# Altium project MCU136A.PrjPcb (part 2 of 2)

## Sheet MCU136A_Connector.SchDoc
size A3; Date: Not shown in title block; ApprovedBy: Not shown in title block; CheckedBy: Not shown in title block; Author: Not shown in title block; CompanyName: Not shown in title block; Engineer: Not shown in title block; Organization: Not shown in title block; Address1: Not shown in title block; Address2: Not shown in title block; Address3: Not shown in title block; Address4: Not shown in title block; DocumentNumber: 3; Revision: Use project parameter SCH_Rev; SheetNumber: 3; SheetTotal: 5; PageSetup: Record=PageOptions¦CenterHorizontal=True¦CenterVertical=True¦PrintScale=1.00¦XCorrection=1.00¦YCorrection=1.00¦PrintKind=0¦BorderSize=5000000¦LeftOffset=0¦BottomOffset=0¦Orientation=2¦PaperLength=1000¦PaperWidth=1000¦Scale=100¦PaperSource=15¦PrintQuality=600¦MediaType=1¦DitherType=10¦PaperKind=Letter¦PrintScaleMode=1
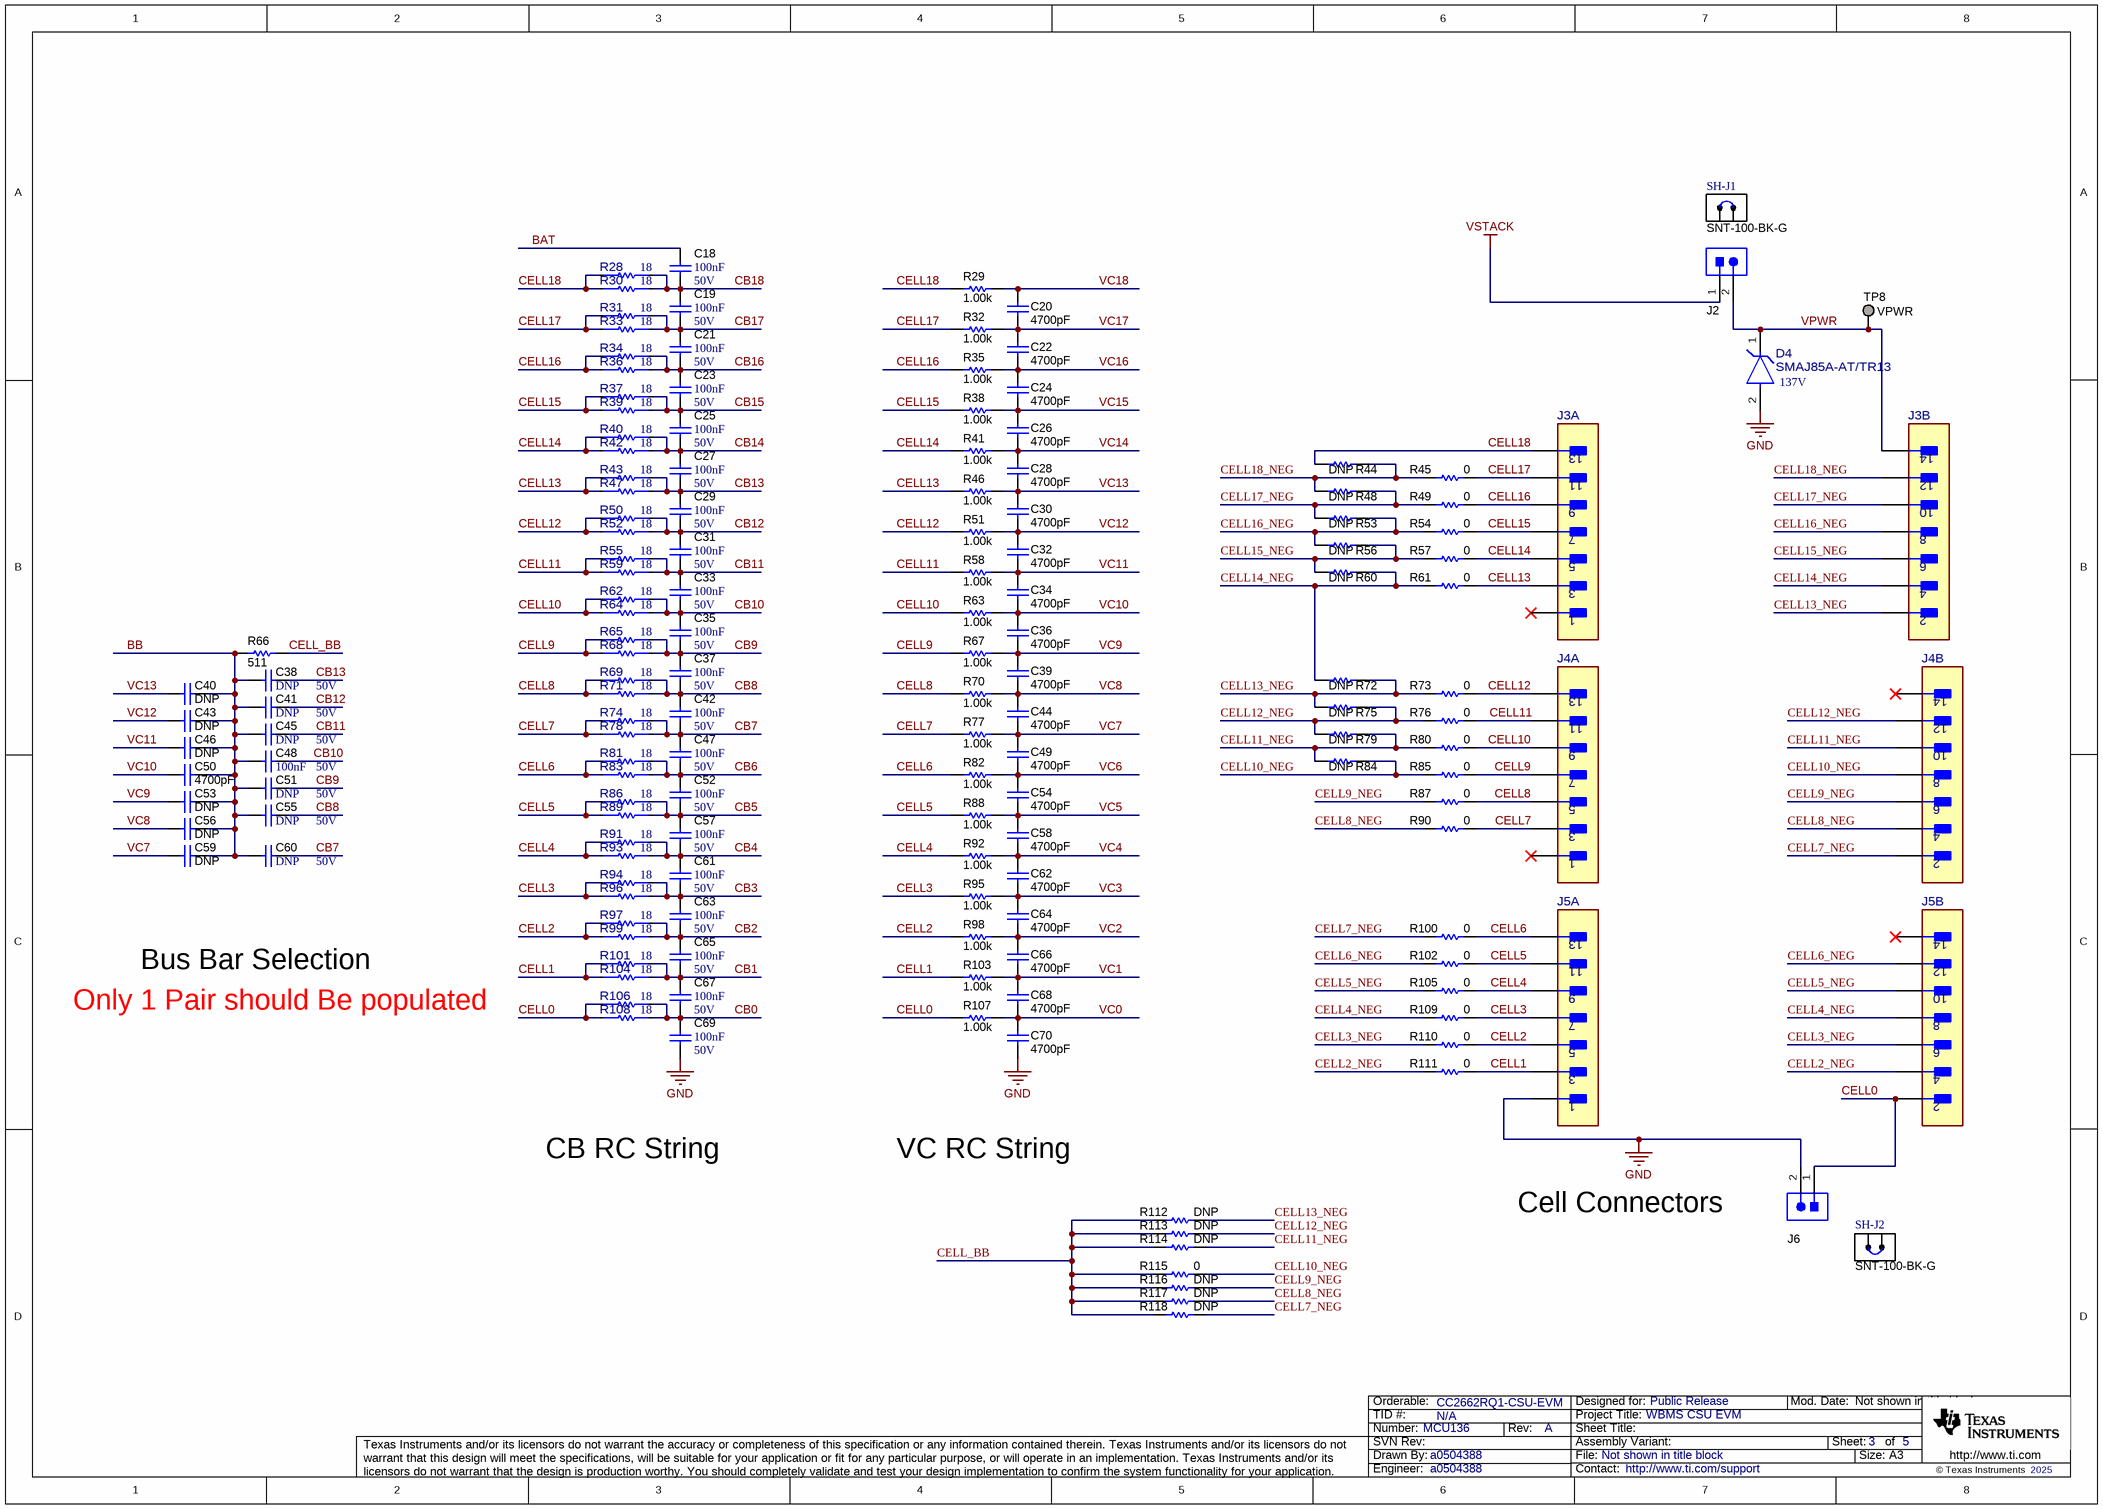
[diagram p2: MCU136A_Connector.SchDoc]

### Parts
C18  Cap_F: 100nF  VDC_V: 50V  [0603]  (hidden comment: GCM188R71H104KA57D)
C19  Cap_F: 100nF  VDC_V: 50V  [0603]  (hidden comment: GCM188R71H104KA57D)
C20  ValueDisplayed: 4700pF  [0402]  (hidden comment: GCM155R71H472KA37D)
C21  Cap_F: 100nF  VDC_V: 50V  [0603]  (hidden comment: GCM188R71H104KA57D)
C22  ValueDisplayed: 4700pF  [0402]  (hidden comment: GCM155R71H472KA37D)
C23  Cap_F: 100nF  VDC_V: 50V  [0603]  (hidden comment: GCM188R71H104KA57D)
C24  ValueDisplayed: 4700pF  [0402]  (hidden comment: GCM155R71H472KA37D)
C25  Cap_F: 100nF  VDC_V: 50V  [0603]  (hidden comment: GCM188R71H104KA57D)
C26  ValueDisplayed: 4700pF  [0402]  (hidden comment: GCM155R71H472KA37D)
C27  Cap_F: 100nF  VDC_V: 50V  [0603]  (hidden comment: GCM188R71H104KA57D)
C28  ValueDisplayed: 4700pF  [0402]  (hidden comment: GCM155R71H472KA37D)
C29  Cap_F: 100nF  VDC_V: 50V  [0603]  (hidden comment: GCM188R71H104KA57D)
C30  ValueDisplayed: 4700pF  [0402]  (hidden comment: GCM155R71H472KA37D)
C31  Cap_F: 100nF  VDC_V: 50V  [0603]  (hidden comment: GCM188R71H104KA57D)
C32  ValueDisplayed: 4700pF  [0402]  (hidden comment: GCM155R71H472KA37D)
C33  Cap_F: 100nF  VDC_V: 50V  [0603]  (hidden comment: GCM188R71H104KA57D)
C34  ValueDisplayed: 4700pF  [0402]  (hidden comment: GCM155R71H472KA37D)
C35  Cap_F: 100nF  VDC_V: 50V  [0603]  (hidden comment: GCM188R71H104KA57D)
C36  ValueDisplayed: 4700pF  [0402]  (hidden comment: GCM155R71H472KA37D)
C37  Cap_F: 100nF  VDC_V: 50V  [0603]  (hidden comment: GCM188R71H104KA57D)
C38  VDC_V: 50V  ValueDisplayed: DNP  [0603]  (hidden comment: GCM188R71H104KA57D)
C39  ValueDisplayed: 4700pF  [0402]  (hidden comment: GCM155R71H472KA37D)
C40  ValueDisplayed: DNP  [0402]  (hidden comment: GCM155R71H472KA37D)
C41  VDC_V: 50V  ValueDisplayed: DNP  [0603]  (hidden comment: GCM188R71H104KA57D)
C42  Cap_F: 100nF  VDC_V: 50V  [0603]  (hidden comment: GCM188R71H104KA57D)
C43  ValueDisplayed: DNP  [0402]  (hidden comment: GCM155R71H472KA37D)
C44  ValueDisplayed: 4700pF  [0402]  (hidden comment: GCM155R71H472KA37D)
C45  VDC_V: 50V  ValueDisplayed: DNP  [0603]  (hidden comment: GCM188R71H104KA57D)
C46  ValueDisplayed: DNP  [0402]  (hidden comment: GCM155R71H472KA37D)
C47  Cap_F: 100nF  VDC_V: 50V  [0603]  (hidden comment: GCM188R71H104KA57D)
C48  Cap_F: 100nF  VDC_V: 50V  [0603]  (hidden comment: GCM188R71H104KA57D)
C49  ValueDisplayed: 4700pF  [0402]  (hidden comment: GCM155R71H472KA37D)
C50  ValueDisplayed: 4700pF  [0402]  (hidden comment: GCM155R71H472KA37D)
C51  VDC_V: 50V  ValueDisplayed: DNP  [0603]  (hidden comment: GCM188R71H104KA57D)
C52  Cap_F: 100nF  VDC_V: 50V  [0603]  (hidden comment: GCM188R71H104KA57D)
C53  ValueDisplayed: DNP  [0402]  (hidden comment: GCM155R71H472KA37D)
C54  ValueDisplayed: 4700pF  [0402]  (hidden comment: GCM155R71H472KA37D)
C55  VDC_V: 50V  ValueDisplayed: DNP  [0603]  (hidden comment: GCM188R71H104KA57D)
C56  ValueDisplayed: DNP  [0402]  (hidden comment: GCM155R71H472KA37D)
C57  Cap_F: 100nF  VDC_V: 50V  [0603]  (hidden comment: GCM188R71H104KA57D)
C58  ValueDisplayed: 4700pF  [0402]  (hidden comment: GCM155R71H472KA37D)
C59  ValueDisplayed: DNP  [0402]  (hidden comment: GCM155R71H472KA37D)
C60  VDC_V: 50V  ValueDisplayed: DNP  [0603]  (hidden comment: GCM188R71H104KA57D)
C61  Cap_F: 100nF  VDC_V: 50V  [0603]  (hidden comment: GCM188R71H104KA57D)
C62  ValueDisplayed: 4700pF  [0402]  (hidden comment: GCM155R71H472KA37D)
C63  Cap_F: 100nF  VDC_V: 50V  [0603]  (hidden comment: GCM188R71H104KA57D)
C64  ValueDisplayed: 4700pF  [0402]  (hidden comment: GCM155R71H472KA37D)
C65  Cap_F: 100nF  VDC_V: 50V  [0603]  (hidden comment: GCM188R71H104KA57D)
C66  ValueDisplayed: 4700pF  [0402]  (hidden comment: GCM155R71H472KA37D)
C67  Cap_F: 100nF  VDC_V: 50V  [0603]  (hidden comment: GCM188R71H104KA57D)
C68  ValueDisplayed: 4700pF  [0402]  (hidden comment: GCM155R71H472KA37D)
C69  Cap_F: 100nF  VDC_V: 50V  [0603]  (hidden comment: GCM188R71H104KA57D)
C70  ValueDisplayed: 4700pF  [0402]  (hidden comment: GCM155R71H472KA37D)
D4  SMAJ85A-AT/TR13  Clamping Voltage: 137V  [FP-SMAJ85A-AT/TR13_SMA-MFG]
J2  PEC02SAAN  [CONN_PEC02SAAN]  (value not drawn)
J3  S14B-PUDSS-1(LF)(SN)  [FP-S14B-PUDSS-1(LF)(SN)_CONN_HDR14-MFG]  (value not drawn)  (parts A,B of 2)
J4  S14B-PUDSS-1(LF)(SN)  [FP-S14B-PUDSS-1(LF)(SN)_CONN_HDR14-MFG]  (value not drawn)  (parts A,B of 2)
J5  S14B-PUDSS-1(LF)(SN)  [FP-S14B-PUDSS-1(LF)(SN)_CONN_HDR14-MFG]  (value not drawn)  (parts A,B of 2)
J6  PEC02SAAN  [CONN_PEC02SAAN]  (value not drawn)
R28  value 18  [FP-CRCW120618R0FKEA_1206-MFG]  (hidden comment: CRCW120618R0FKEA)
R29  ValueDisplayed: 1.00k  [0402]  (hidden comment: CRCW04021K00FKED)
R30  value 18  [FP-CRCW120618R0FKEA_1206-MFG]  (hidden comment: CRCW120618R0FKEA)
R31  value 18  [FP-CRCW120618R0FKEA_1206-MFG]  (hidden comment: CRCW120618R0FKEA)
R32  ValueDisplayed: 1.00k  [0402]  (hidden comment: CRCW04021K00FKED)
R33  value 18  [FP-CRCW120618R0FKEA_1206-MFG]  (hidden comment: CRCW120618R0FKEA)
R34  value 18  [FP-CRCW120618R0FKEA_1206-MFG]  (hidden comment: CRCW120618R0FKEA)
R35  ValueDisplayed: 1.00k  [0402]  (hidden comment: CRCW04021K00FKED)
R36  value 18  [FP-CRCW120618R0FKEA_1206-MFG]  (hidden comment: CRCW120618R0FKEA)
R37  value 18  [FP-CRCW120618R0FKEA_1206-MFG]  (hidden comment: CRCW120618R0FKEA)
R38  ValueDisplayed: 1.00k  [0402]  (hidden comment: CRCW04021K00FKED)
R39  value 18  [FP-CRCW120618R0FKEA_1206-MFG]  (hidden comment: CRCW120618R0FKEA)
R40  value 18  [FP-CRCW120618R0FKEA_1206-MFG]  (hidden comment: CRCW120618R0FKEA)
R41  ValueDisplayed: 1.00k  [0402]  (hidden comment: CRCW04021K00FKED)
R42  value 18  [FP-CRCW120618R0FKEA_1206-MFG]  (hidden comment: CRCW120618R0FKEA)
R43  value 18  [FP-CRCW120618R0FKEA_1206-MFG]  (hidden comment: CRCW120618R0FKEA)
R44  ValueDisplayed: DNP  [0805_HV]  (hidden comment: CRCW08050000Z0EA)
R45  ValueDisplayed: 0  [0805_HV]  (hidden comment: CRCW08050000Z0EA)
R46  ValueDisplayed: 1.00k  [0402]  (hidden comment: CRCW04021K00FKED)
R47  value 18  [FP-CRCW120618R0FKEA_1206-MFG]  (hidden comment: CRCW120618R0FKEA)
R48  ValueDisplayed: DNP  [0805_HV]  (hidden comment: CRCW08050000Z0EA)
R49  ValueDisplayed: 0  [0805_HV]  (hidden comment: CRCW08050000Z0EA)
R50  value 18  [FP-CRCW120618R0FKEA_1206-MFG]  (hidden comment: CRCW120618R0FKEA)
R51  ValueDisplayed: 1.00k  [0402]  (hidden comment: CRCW04021K00FKED)
R52  value 18  [FP-CRCW120618R0FKEA_1206-MFG]  (hidden comment: CRCW120618R0FKEA)
R53  ValueDisplayed: DNP  [0805_HV]  (hidden comment: CRCW08050000Z0EA)
R54  ValueDisplayed: 0  [0805_HV]  (hidden comment: CRCW08050000Z0EA)
R55  value 18  [FP-CRCW120618R0FKEA_1206-MFG]  (hidden comment: CRCW120618R0FKEA)
R56  ValueDisplayed: DNP  [0805_HV]  (hidden comment: CRCW08050000Z0EA)
R57  ValueDisplayed: 0  [0805_HV]  (hidden comment: CRCW08050000Z0EA)
R58  ValueDisplayed: 1.00k  [0402]  (hidden comment: CRCW04021K00FKED)
R59  value 18  [FP-CRCW120618R0FKEA_1206-MFG]  (hidden comment: CRCW120618R0FKEA)
R60  ValueDisplayed: DNP  [0805_HV]  (hidden comment: CRCW08050000Z0EA)
R61  ValueDisplayed: 0  [0805_HV]  (hidden comment: CRCW08050000Z0EA)
R62  value 18  [FP-CRCW120618R0FKEA_1206-MFG]  (hidden comment: CRCW120618R0FKEA)
R63  ValueDisplayed: 1.00k  [0402]  (hidden comment: CRCW04021K00FKED)
R64  value 18  [FP-CRCW120618R0FKEA_1206-MFG]  (hidden comment: CRCW120618R0FKEA)
R65  value 18  [FP-CRCW120618R0FKEA_1206-MFG]  (hidden comment: CRCW120618R0FKEA)
R66  ValueDisplayed: 511  [0402]  (hidden comment: CRCW0402511RFKED)
R67  ValueDisplayed: 1.00k  [0402]  (hidden comment: CRCW04021K00FKED)
R68  value 18  [FP-CRCW120618R0FKEA_1206-MFG]  (hidden comment: CRCW120618R0FKEA)
R69  value 18  [FP-CRCW120618R0FKEA_1206-MFG]  (hidden comment: CRCW120618R0FKEA)
R70  ValueDisplayed: 1.00k  [0402]  (hidden comment: CRCW04021K00FKED)
R71  value 18  [FP-CRCW120618R0FKEA_1206-MFG]  (hidden comment: CRCW120618R0FKEA)
R72  ValueDisplayed: DNP  [0805_HV]  (hidden comment: CRCW08050000Z0EA)
R73  ValueDisplayed: 0  [0805_HV]  (hidden comment: CRCW08050000Z0EA)
R74  value 18  [FP-CRCW120618R0FKEA_1206-MFG]  (hidden comment: CRCW120618R0FKEA)
R75  ValueDisplayed: DNP  [0805_HV]  (hidden comment: CRCW08050000Z0EA)
R76  ValueDisplayed: 0  [0805_HV]  (hidden comment: CRCW08050000Z0EA)
R77  ValueDisplayed: 1.00k  [0402]  (hidden comment: CRCW04021K00FKED)
R78  value 18  [FP-CRCW120618R0FKEA_1206-MFG]  (hidden comment: CRCW120618R0FKEA)
R79  ValueDisplayed: DNP  [0805_HV]  (hidden comment: CRCW08050000Z0EA)
R80  ValueDisplayed: 0  [0805_HV]  (hidden comment: CRCW08050000Z0EA)
R81  value 18  [FP-CRCW120618R0FKEA_1206-MFG]  (hidden comment: CRCW120618R0FKEA)
R82  ValueDisplayed: 1.00k  [0402]  (hidden comment: CRCW04021K00FKED)
R83  value 18  [FP-CRCW120618R0FKEA_1206-MFG]  (hidden comment: CRCW120618R0FKEA)
R84  ValueDisplayed: DNP  [0805_HV]  (hidden comment: CRCW08050000Z0EA)
R85  ValueDisplayed: 0  [0805_HV]  (hidden comment: CRCW08050000Z0EA)
R86  value 18  [FP-CRCW120618R0FKEA_1206-MFG]  (hidden comment: CRCW120618R0FKEA)
R87  ValueDisplayed: 0  [0805_HV]  (hidden comment: CRCW08050000Z0EA)
R88  ValueDisplayed: 1.00k  [0402]  (hidden comment: CRCW04021K00FKED)
R89  value 18  [FP-CRCW120618R0FKEA_1206-MFG]  (hidden comment: CRCW120618R0FKEA)
R90  ValueDisplayed: 0  [0805_HV]  (hidden comment: CRCW08050000Z0EA)
R91  value 18  [FP-CRCW120618R0FKEA_1206-MFG]  (hidden comment: CRCW120618R0FKEA)
R92  ValueDisplayed: 1.00k  [0402]  (hidden comment: CRCW04021K00FKED)
R93  value 18  [FP-CRCW120618R0FKEA_1206-MFG]  (hidden comment: CRCW120618R0FKEA)
R94  value 18  [FP-CRCW120618R0FKEA_1206-MFG]  (hidden comment: CRCW120618R0FKEA)
R95  ValueDisplayed: 1.00k  [0402]  (hidden comment: CRCW04021K00FKED)
R96  value 18  [FP-CRCW120618R0FKEA_1206-MFG]  (hidden comment: CRCW120618R0FKEA)
R97  value 18  [FP-CRCW120618R0FKEA_1206-MFG]  (hidden comment: CRCW120618R0FKEA)
R98  ValueDisplayed: 1.00k  [0402]  (hidden comment: CRCW04021K00FKED)
R99  value 18  [FP-CRCW120618R0FKEA_1206-MFG]  (hidden comment: CRCW120618R0FKEA)
R100  ValueDisplayed: 0  [0805_HV]  (hidden comment: CRCW08050000Z0EA)
R101  value 18  [FP-CRCW120618R0FKEA_1206-MFG]  (hidden comment: CRCW120618R0FKEA)
R102  ValueDisplayed: 0  [0805_HV]  (hidden comment: CRCW08050000Z0EA)
R103  ValueDisplayed: 1.00k  [0402]  (hidden comment: CRCW04021K00FKED)
R104  value 18  [FP-CRCW120618R0FKEA_1206-MFG]  (hidden comment: CRCW120618R0FKEA)
R105  ValueDisplayed: 0  [0805_HV]  (hidden comment: CRCW08050000Z0EA)
R106  value 18  [FP-CRCW120618R0FKEA_1206-MFG]  (hidden comment: CRCW120618R0FKEA)
R107  ValueDisplayed: 1.00k  [0402]  (hidden comment: CRCW04021K00FKED)
R108  value 18  [FP-CRCW120618R0FKEA_1206-MFG]  (hidden comment: CRCW120618R0FKEA)
R109  ValueDisplayed: 0  [0805_HV]  (hidden comment: CRCW08050000Z0EA)
R110  ValueDisplayed: 0  [0805_HV]  (hidden comment: CRCW08050000Z0EA)
R111  ValueDisplayed: 0  [0805_HV]  (hidden comment: CRCW08050000Z0EA)
R112  ValueDisplayed: DNP  [0805_HV]  (hidden comment: CRCW08050000Z0EA)
R113  ValueDisplayed: DNP  [0805_HV]  (hidden comment: CRCW08050000Z0EA)
R114  ValueDisplayed: DNP  [0805_HV]  (hidden comment: CRCW08050000Z0EA)
R115  ValueDisplayed: 0  [0805_HV]  (hidden comment: CRCW08050000Z0EA)
R116  ValueDisplayed: DNP  [0805_HV]  (hidden comment: CRCW08050000Z0EA)
R117  ValueDisplayed: DNP  [0805_HV]  (hidden comment: CRCW08050000Z0EA)
R118  ValueDisplayed: DNP  [0805_HV]  (hidden comment: CRCW08050000Z0EA)
SH-J1  SNT-100-BK-G  [SNT-100-BK-G]
SH-J2  SNT-100-BK-G  [SNT-100-BK-G]
TP8  VPWR  [Keystone1598-2]

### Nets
GND: C69.2 C70.2 D4.2(ANODE) J5.1 J6.2
VSTACK: J2.1  [project net CELL18_Lad]
BAT: C18.1
BB: C38.1 C40.2 C41.1 C43.2 C45.1 C46.2 C48.1 C50.2 C51.1 C53.2 C55.1 C56.2 C59.2 C60.1 R66.1
CB0: C67.2 C69.1 R106.2 R108.2
CB1: C65.2 C67.1 R101.2 R104.2
CB2: C63.2 C65.1 R97.2 R99.2
CB3: C61.2 C63.1 R94.2 R96.2
CB4: C57.2 C61.1 R91.2 R93.2
CB5: C52.2 C57.1 R86.2 R89.2
CB6: C47.2 C52.1 R81.2 R83.2
CB7: C42.2 C47.1 C60.2 R74.2 R78.2
CB8: C37.2 C42.1 C55.2 R69.2 R71.2
CB9: C35.2 C37.1 C51.2 R65.2 R68.2
CB10: C33.2 C35.1 C48.2 R62.2 R64.2
CB11: C31.2 C33.1 C45.2 R55.2 R59.2
CB12: C29.2 C31.1 C41.2 R50.2 R52.2
CB13: C27.2 C29.1 C38.2 R43.2 R47.2
CB14: C25.2 C27.1 R40.2 R42.2
CB15: C23.2 C25.1 R37.2 R39.2
CB16: C21.2 C23.1 R34.2 R36.2
CB17: C19.2 C21.1 R31.2 R33.2
CB18: C18.2 C19.1 R28.2 R30.2
CELL0: J5.2 J6.1 R106.1 R107.1 R108.1
CELL1: J5.3 R101.1 R103.1 R104.1 R111.2
CELL2: J5.5 R97.1 R98.1 R99.1 R110.2
CELL2_NEG: J5.4 R111.1
CELL3: J5.7 R94.1 R95.1 R96.1 R109.2
CELL3_NEG: J5.6 R110.1
CELL4: J5.9 R91.1 R92.1 R93.1 R105.2
CELL4_NEG: J5.8 R109.1
CELL5: J5.11 R86.1 R88.1 R89.1 R102.2
CELL5_NEG: J5.10 R105.1
CELL6: J5.13 R81.1 R82.1 R83.1 R100.2
CELL6_NEG: J5.12 R102.1
CELL7: J4.3 R74.1 R77.1 R78.1 R90.2
CELL7_NEG: J4.2 R100.1 R118.2
CELL8: J4.5 R69.1 R70.1 R71.1 R87.2
CELL8_NEG: J4.4 R90.1 R117.2
CELL9: J4.7 R65.1 R67.1 R68.1 R85.2
CELL9_NEG: J4.6 R87.1 R116.2
CELL10: J4.9 R62.1 R63.1 R64.1 R80.2
CELL10_NEG: J4.8 R84.2 R85.1 R115.2
CELL11: J4.11 R55.1 R58.1 R59.1 R76.2
CELL11_NEG: J4.10 R79.2 R80.1 R84.1 R114.2
CELL12: J4.13 R50.1 R51.1 R52.1 R73.2
CELL12_NEG: J4.12 R75.2 R76.1 R79.1 R113.2
CELL13: J3.3 R43.1 R46.1 R47.1 R61.2
CELL13_NEG: J3.2 R72.2 R73.1 R75.1 R112.2
CELL14: J3.5 R40.1 R41.1 R42.1 R57.1
CELL14_NEG: J3.4 R60.2 R61.1 R72.1
CELL15: J3.7 R37.1 R38.1 R39.1 R54.1
CELL15_NEG: J3.6 R56.2 R57.2 R60.1
CELL16: J3.9 R34.1 R35.1 R36.1 R49.1
CELL16_NEG: J3.8 R53.2 R54.2 R56.1
CELL17: J3.11 R31.1 R32.1 R33.1 R45.1
CELL17_NEG: J3.10 R48.2 R49.2 R53.1
CELL18: J3.13 R28.1 R29.1 R30.1 R44.1
CELL18_NEG: J3.12 R44.2 R45.2 R48.1
CELL_BB: R66.2 R112.1 R113.1 R114.1 R115.1 R116.1 R117.1 R118.1
VC0: C68.2 C70.1 R107.2
VC1: C66.2 C68.1 R103.2
VC2: C64.2 C66.1 R98.2
VC3: C62.2 C64.1 R95.2
VC4: C58.2 C62.1 R92.2
VC5: C54.2 C58.1 R88.2
VC6: C49.2 C54.1 R82.2
VC7: C44.2 C49.1 C59.1 R77.2
VC8: C39.2 C44.1 C56.1 R70.2
VC9: C36.2 C39.1 C53.1 R67.2
VC10: C34.2 C36.1 C50.1 R63.2
VC11: C32.2 C34.1 C46.1 R58.2
VC12: C30.2 C32.1 C43.1 R51.2
VC13: C28.2 C30.1 C40.1 R46.2
VC14: C26.2 C28.1 R41.2
VC15: C24.2 C26.1 R38.2
VC16: C22.2 C24.1 R35.2
VC17: C20.2 C22.1 R32.2
VC18: C20.1 R29.2
VPWR: D4.1(CATHODE) J2.2 J3.14 TP8.1

Not connected (* = marked no-connect by the designer): J3 1*; J4 1* 14*; J5 14*

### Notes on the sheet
- Bus Bar Selection
- Only 1 Pair should Be populated
- CB RC String
- VC RC String
- Cell Connectors

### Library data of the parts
C18 C19 C21 C23 C25 C27 C29 C31 C33 C35 C37 C42 C47 C48 C52 C57 C61 C63 C65 C67 C69 = CMP-0007144-4: CAP, CERM, 0.1 uF, 50 V, +/- 10%, X7R, 0603; Manufacturer: MuRata; TaMin_C: -55°C; ESR_ohm: 0.02; Polarized: N; SizeAreaWB_mm2: 4.68; Value1: 0.02 ohm; U/M: EA; Value: 0.1uF; TaMax_C: 125°C; SizeZ_mm: 1; SizeX_mm: 1.6; SizeY_mm: 0.8; SizeArea_mm2: 1.28; IRMS_A: 1.84A; AEC Category: Q200
C20 C22 C24 C26 C28 C30 C32 C34 C36 C39 C40 C43 C44 C46 C49 C50 C53 C54 C56 C58 C59 C62 C64 C66 C68 C70 = CMP-0006361-2: CAP, CERM, 4700 pF, 50 V, +/- 10%, X7R, AEC-Q200 Grade 1, 0402; Manufacturer: MuRata; TaMin_C: -55°C; Polarized: N; SizeAreaWB_mm2: 3; Value1: Unknown; U/M: EA; Value: 4700pF; TaMax_C: 125°C; SizeZ_mm: 0.6; SizeX_mm: 1; SizeY_mm: 0.5; Value2: 50V; AEC Qualified: Y; Cap_F: 4.7nF; AEC Category: Q200
C38 C41 C45 C51 C55 C60 = CMP-0007144-4: CAP, CERM, 0.1 uF, 50 V, +/- 10%, X7R, 0603; Manufacturer: MuRata; TaMin_C: -55°C; ESR_ohm: 0.02; Polarized: N; SizeAreaWB_mm2: 4.68; Value1: 0.02 ohm; U/M: EA; Value: 0.1uF; TaMax_C: 125°C; SizeZ_mm: 1; SizeX_mm: 1.6; SizeY_mm: 0.8; SizeArea_mm2: 1.28; Cap_F: 100nF; IRMS_A: 1.84A; AEC Category: Q200
D4 = CMP-0121790-1: 137V Clamp 2.9A Ipp Tvs Diode Surface Mount DO-214AC (SMA); Manufacturer: YAGEO; AEC Qualified: Yes; SizeZ_mm: 2.5mm; VRWM: 85V; Ppk: 400W; AEC Grade: Grade 0; Breakdown Voltage: 94.4V; Direction: Unidirectional; Number Of Channels: 1; TJmax_C: +150°C
J2 J6 = CMP-0002337-1: Header, 100mil, 2x1, Tin, TH; Manufacturer: Sullins Connector Solutions; CNHeader: TRUE; Current_A: 3A; Green_Lifecycle: Not Set; Shrouded: N; Gender: Male; Green_REACh: Incomplete; Voltage_V: 1.8kV; Row_Count: 1; Pitch_mm: 2.54; CT: FALSE; Cert_UL: Y
J3-J5 = CMP-0096844-1: 14 Position Dual Row Side Entry 2 mm Through Hole Shrouded Header; Manufacturer: JST; DUT-Pitch_mm: 2mm; SizeZ_mm: 8.5mm; Row_Count: 2; ContactFinish: Tin,Copper; Current_A: 3A; Voltage_V: 250V; AEC Qualified: No; Conn Orientation: Horizontal; Conn Gender: Male
R28 R30 R31 R33 R34 R36 R37 R39 R40 R42 R43 R47 R50 R52 R55 R59 R62 R64 R65 R68 R69 R71 R74 R78 R81 R83 R86 R89 R91 R93 R94 R96 R97 R99 R101 R104 R106 R108 = CMP-0121789-1: RES Thick Film, 18Ω, 1%, 0.25W, 100ppm/°C, 1206; Manufacturer: Vishay; AEC Grade: Grade 0; AEC Qualified: Yes; Power_W: 250mW; SizeZ_mm: 0.6mm; VDC_V: 200V
R29 R32 R35 R38 R41 R46 R51 R58 R63 R67 R70 R77 R82 R88 R92 R95 R98 R103 R107 = CMP-0026071-3: RES, 1.00 k, 1%, 0.063 W, AEC-Q200 Grade 0, 0402; Manufacturer: Vishay-Dale; Power_W: 63mW; TempCo: 100 ppm/C; Value_Code: 1k00; Value: 1.00k; EIA_Code: E96; Res_ohm: 1k; SizeX_mm: 1; SizeY_mm: 0.5; SizeZ_mm: 0.6; Value2: 0.063W; AEC Qualified: Y; VDC_V: 50V; AEC Category: Q200; AEC Grade: 0
R44 R45 R48 R49 R53 R54 R56 R57 R60 R61 R72 R73 R75 R76 R79 R80 R84 R85 R87 R90 R100 R102 R105 R109-R118 = CMP-0020442-3: RES, 0, 5%, 0.125 W, AEC-Q200 Grade 0, 0805; Manufacturer: Vishay-Dale; Power_W: 125mW; TempCo: 200 ppm/C; Value_Code: 0000; Value: 0; EIA_Code: E24; SizeX_mm: 2; SizeY_mm: 1.25; SizeZ_mm: 1.45; Value2: 0.125W; SizeArea_mm2: 2.5; AEC Qualified: Y; VDC_V: 150V; AEC Category: Q200
R66 = CMP-0026436-2: RES, 511, 1%, 0.063 W, AEC-Q200 Grade 0, 0402; Manufacturer: Vishay-Dale; Power_W: 63mW; TempCo: 100 ppm/C; Value_Code: 511R; Value: 511; EIA_Code: E96; SizeX_mm: 1; SizeY_mm: 0.5; SizeZ_mm: 0.6; Value2: 0.063W; AEC Qualified: Y; VDC_V: 50V; AEC Category: Q200; AEC Grade: 0
SH-J1 SH-J2 = CMP-0003623-3: Shunt, 100mil, Gold plated, Black; Alternate PartNumber: 969102-0000-DA; Manufacturer: Samtec; Alternate Manufacturer: 3M; Value: 1x2; Note: You can "mate" this to a header by matching the designator.  i.e. use SH-J3 for header J3
TP8 = CMP-0055121-1: Terminal, Turret, TH, Triple; Manufacturer: Keystone; PartNumber: 1598-2; CT: FALSE; Green_REACh: Passed; CompType: Turret Terminal; Green_Lifecycle: Active

## Sheet MCU136A_Resistive_Ladder.SchDoc
size A3; Date: Not shown in title block; ApprovedBy: Not shown in title block; CheckedBy: Not shown in title block; Author: Not shown in title block; CompanyName: Not shown in title block; Engineer: Not shown in title block; Organization: Not shown in title block; Address1: Not shown in title block; Address2: Not shown in title block; Address3: Not shown in title block; Address4: Not shown in title block; DocumentNumber: 1; Revision: Use project parameter SCH_Rev; SheetNumber: 3; SheetTotal: 6; PageSetup: Record=PageOptions¦CenterHorizontal=True¦CenterVertical=True¦PrintScale=0.69¦XCorrection=1.00¦YCorrection=1.00¦PrintKind=0¦BorderSize=5000000¦LeftOffset=0¦BottomOffset=0¦Orientation=2¦PaperLength=1000¦PaperWidth=1000¦Scale=100¦PaperSource=15¦PrintQuality=600¦MediaType=1¦DitherType=10¦PaperKind=Letter¦PrintScaleMode=1
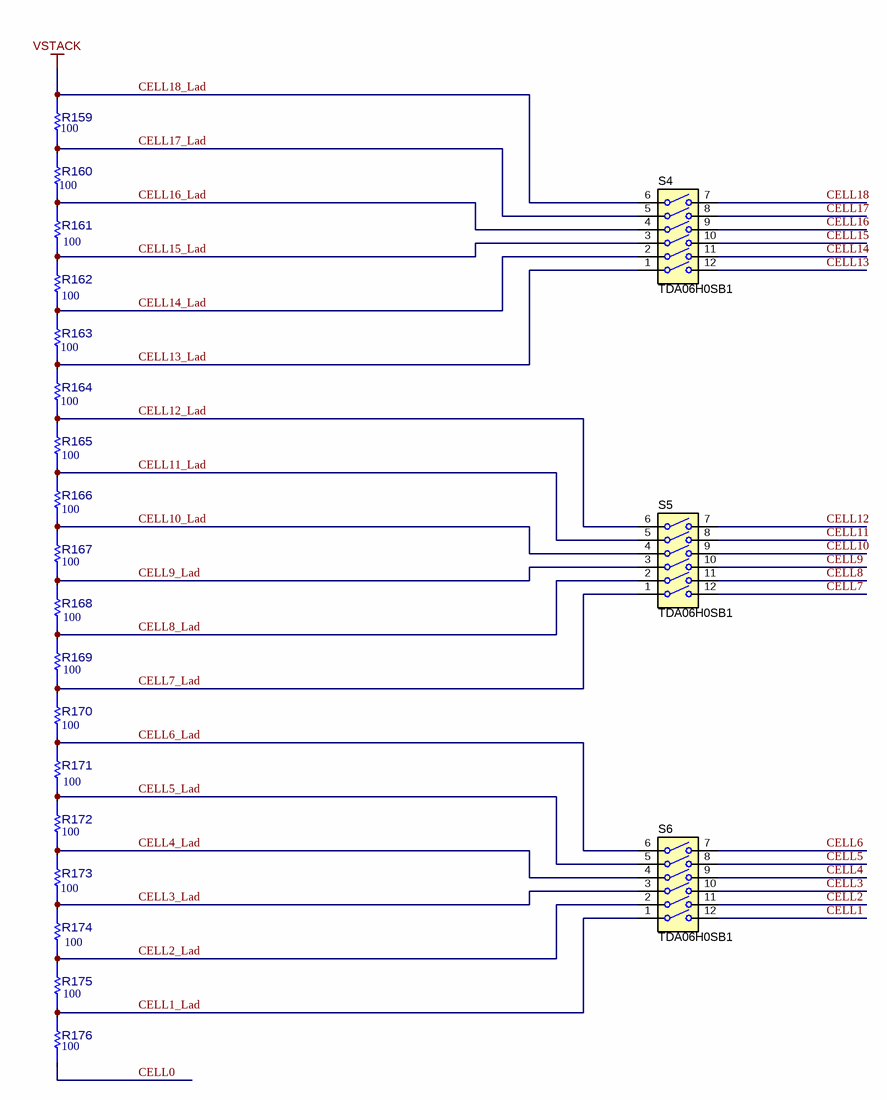
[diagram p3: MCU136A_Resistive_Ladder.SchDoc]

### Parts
R159  value 100  [FP-CRCW2010100RFKEFHP_2010-MFG]  (hidden comment: CRCW2010100RFKEFHP)
R160  value 100  [FP-CRCW2010100RFKEFHP_2010-MFG]  (hidden comment: CRCW2010100RFKEFHP)
R161  value 100  [FP-CRCW2010100RFKEFHP_2010-MFG]  (hidden comment: CRCW2010100RFKEFHP)
R162  value 100  [FP-CRCW2010100RFKEFHP_2010-MFG]  (hidden comment: CRCW2010100RFKEFHP)
R163  value 100  [FP-CRCW2010100RFKEFHP_2010-MFG]  (hidden comment: CRCW2010100RFKEFHP)
R164  value 100  [FP-CRCW2010100RFKEFHP_2010-MFG]  (hidden comment: CRCW2010100RFKEFHP)
R165  value 100  [FP-CRCW2010100RFKEFHP_2010-MFG]  (hidden comment: CRCW2010100RFKEFHP)
R166  value 100  [FP-CRCW2010100RFKEFHP_2010-MFG]  (hidden comment: CRCW2010100RFKEFHP)
R167  value 100  [FP-CRCW2010100RFKEFHP_2010-MFG]  (hidden comment: CRCW2010100RFKEFHP)
R168  value 100  [FP-CRCW2010100RFKEFHP_2010-MFG]  (hidden comment: CRCW2010100RFKEFHP)
R169  value 100  [FP-CRCW2010100RFKEFHP_2010-MFG]  (hidden comment: CRCW2010100RFKEFHP)
R170  value 100  [FP-CRCW2010100RFKEFHP_2010-MFG]  (hidden comment: CRCW2010100RFKEFHP)
R171  value 100  [FP-CRCW2010100RFKEFHP_2010-MFG]  (hidden comment: CRCW2010100RFKEFHP)
R172  value 100  [FP-CRCW2010100RFKEFHP_2010-MFG]  (hidden comment: CRCW2010100RFKEFHP)
R173  value 100  [FP-CRCW2010100RFKEFHP_2010-MFG]  (hidden comment: CRCW2010100RFKEFHP)
R174  value 100  [FP-CRCW2010100RFKEFHP_2010-MFG]  (hidden comment: CRCW2010100RFKEFHP)
R175  value 100  [FP-CRCW2010100RFKEFHP_2010-MFG]  (hidden comment: CRCW2010100RFKEFHP)
R176  value 100  [FP-CRCW2010100RFKEFHP_2010-MFG]  (hidden comment: CRCW2010100RFKEFHP)
S4  TDA06H0SB1  [SW_TDA06H0SB1]
S5  TDA06H0SB1  [SW_TDA06H0SB1]
S6  TDA06H0SB1  [SW_TDA06H0SB1]

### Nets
CELL18_Lad: R159.2 S4.6  [also labelled VSTACK]
CELL0: R176.1
CELL1: S6.12(1A)
CELL1_Lad: R175.1 R176.2 S6.1
CELL2: S6.11(2A)
CELL2_Lad: R174.1 R175.2 S6.2
CELL3: S6.10(3A)
CELL3_Lad: R173.1 R174.2 S6.3
CELL4: S6.9(4A)
CELL4_Lad: R172.1 R173.2 S6.4
CELL5: S6.8(5A)
CELL5_Lad: R171.1 R172.2 S6.5
CELL6: S6.7(6A)
CELL6_Lad: R170.1 R171.2 S6.6
CELL7: S5.12(1A)
CELL7_Lad: R169.1 R170.2 S5.1
CELL8: S5.11(2A)
CELL8_Lad: R168.1 R169.2 S5.2
CELL9: S5.10(3A)
CELL9_Lad: R167.1 R168.2 S5.3
CELL10: S5.9(4A)
CELL10_Lad: R166.1 R167.2 S5.4
CELL11: S5.8(5A)
CELL11_Lad: R165.1 R166.2 S5.5
CELL12: S5.7(6A)
CELL12_Lad: R164.1 R165.2 S5.6
CELL13: S4.12(1A)
CELL13_Lad: R163.1 R164.2 S4.1
CELL14: S4.11(2A)
CELL14_Lad: R162.1 R163.2 S4.2
CELL15: S4.10(3A)
CELL15_Lad: R161.1 R162.2 S4.3
CELL16: S4.9(4A)
CELL16_Lad: R160.1 R161.2 S4.4
CELL17: S4.8(5A)
CELL17_Lad: R159.1 R160.2 S4.5
CELL18: S4.7(6A)

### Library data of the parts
R159-R176 = CMP-0121409-1: RES Thick Film, 100Ω, 1%, 1W, 100ppm/°C, 2010; Manufacturer: Vishay Dale; AEC Grade: Grade 0; AEC Qualified: Yes; SizeZ_mm: 0.7mm; VDC_V: 400V
S4-S6 = CMP-0002278-1: DIP Switch, SPST, 6Pos, Slide, SMT; Manufacturer: C&K Components; CurrentRating_mA: 25A; PositionCount: 6; VDC_V: 24V; SwitchFunction: Off-On

## Sheet MCU136A_Communication.SchDoc
size A3; Date: Not shown in title block; ApprovedBy: Not shown in title block; CheckedBy: Not shown in title block; Author: Not shown in title block; CompanyName: Not shown in title block; Engineer: Not shown in title block; Organization: Not shown in title block; Address1: Not shown in title block; Address2: Not shown in title block; Address3: Not shown in title block; Address4: Not shown in title block; DocumentNumber: 4; Revision: Use project parameter SCH_Rev; SheetNumber: 5; SheetTotal: 6; PageSetup: Record=PageOptions¦CenterHorizontal=True¦CenterVertical=True¦PrintScale=1.00¦XCorrection=1.00¦YCorrection=1.00¦PrintKind=0¦BorderSize=5000000¦LeftOffset=0¦BottomOffset=0¦Orientation=2¦PaperLength=1000¦PaperWidth=1000¦Scale=100¦PaperSource=15¦PrintQuality=600¦MediaType=1¦DitherType=10¦PaperKind=Letter¦PrintScaleMode=1
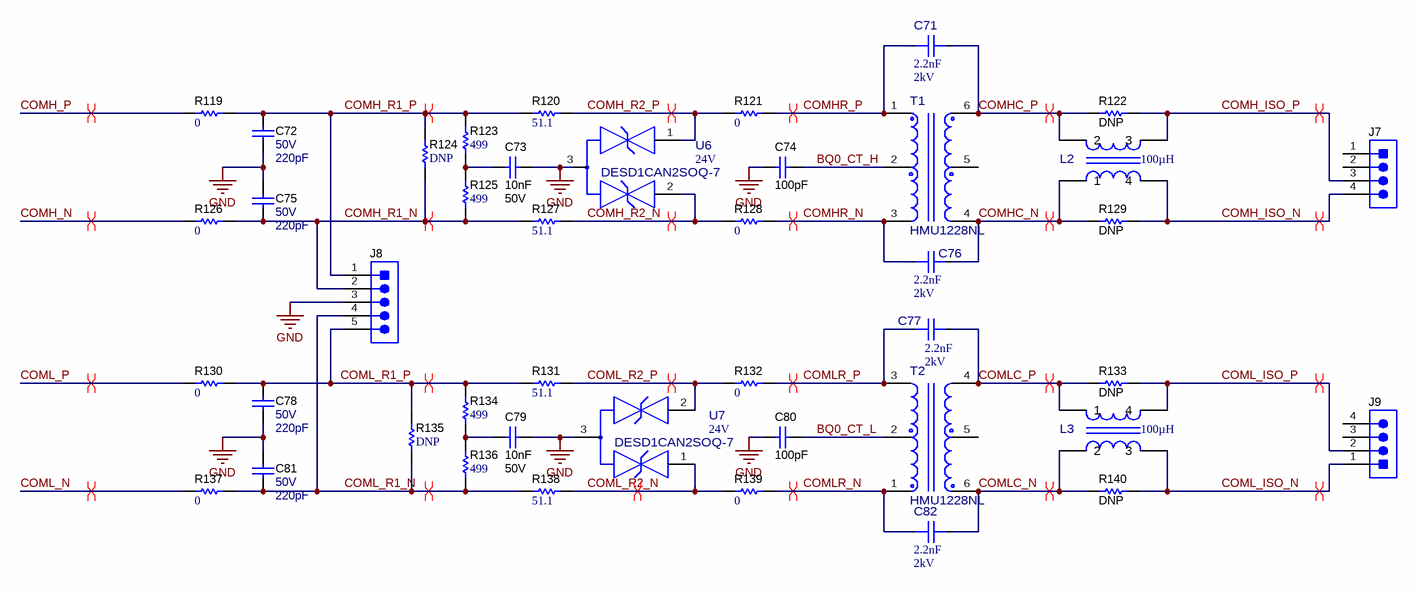
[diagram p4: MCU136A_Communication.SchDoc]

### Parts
C71  ValueDisplayed: 2.2nF  VDC_V: 2kV  [FP-1206Y2K00222KET_1206-MFG]  (hidden comment: 1206Y2K00222KET)
C72  VDC_V: 50V  ValueDisplayed: 220pF  [0402]  (hidden comment: CGA2B2X7R1H221K050BA)
C73  Cap_F: 10nF  VDC_V: 50V  [0603]  (hidden comment: GCM188R71H103KA37D)
C74  ValueDisplayed: 100pF  [0603]  (hidden comment: GCM1885C1H101JA16J)
C75  VDC_V: 50V  ValueDisplayed: 220pF  [0402]  (hidden comment: CGA2B2X7R1H221K050BA)
C76  ValueDisplayed: 2.2nF  VDC_V: 2kV  [FP-1206Y2K00222KET_1206-MFG]  (hidden comment: 1206Y2K00222KET)
C77  ValueDisplayed: 2.2nF  VDC_V: 2kV  [FP-1206Y2K00222KET_1206-MFG]  (hidden comment: 1206Y2K00222KET)
C78  VDC_V: 50V  ValueDisplayed: 220pF  [0402]  (hidden comment: CGA2B2X7R1H221K050BA)
C79  Cap_F: 10nF  VDC_V: 50V  [0603]  (hidden comment: GCM188R71H103KA37D)
C80  ValueDisplayed: 100pF  [0603]  (hidden comment: GCM1885C1H101JA16J)
C81  VDC_V: 50V  ValueDisplayed: 220pF  [0402]  (hidden comment: CGA2B2X7R1H221K050BA)
C82  ValueDisplayed: 2.2nF  VDC_V: 2kV  [FP-1206Y2K00222KET_1206-MFG]  (hidden comment: 1206Y2K00222KET)
J7  70551-0038  [Molex_70551-0038]  (value not drawn)
J8  TSW-105-07-G-S  [TSW-105-07-X-S]  (value not drawn)
J9  70551-0038  [Molex_70551-0038]  (value not drawn)
L2  Ind_H: 100µH  [FP-ACT1210R-101-2P-TL00_SMD4_3MM2_2MM5-MFG]  (hidden comment: ACT1210R-101-2P-TL00)
L3  Ind_H: 100µH  [FP-ACT1210R-101-2P-TL00_SMD4_3MM2_2MM5-MFG]  (hidden comment: ACT1210R-101-2P-TL00)
R119  ValueDisplayed: 0  [0603]  (hidden comment: CRCW06030000Z0EA)
R120  ValueDisplayed: 51.1  [0402]  (hidden comment: CRCW040251R1FKED)
R121  ValueDisplayed: 0  [0603]  (hidden comment: CRCW06030000Z0EA)
R122  ValueDisplayed: DNP  [0603]  (hidden comment: RC0603JR-070RL)
R123  ValueDisplayed: 499  [0603]  (hidden comment: CRCW0603499RFKEA)
R124  ValueDisplayed: DNP  [0603]  (hidden comment: CRCW06031K00FKEA)
R125  ValueDisplayed: 499  [0603]  (hidden comment: CRCW0603499RFKEA)
R126  ValueDisplayed: 0  [0603]  (hidden comment: CRCW06030000Z0EA)
R127  ValueDisplayed: 51.1  [0402]  (hidden comment: CRCW040251R1FKED)
R128  ValueDisplayed: 0  [0603]  (hidden comment: CRCW06030000Z0EA)
R129  ValueDisplayed: DNP  [0603]  (hidden comment: RC0603JR-070RL)
R130  ValueDisplayed: 0  [0603]  (hidden comment: CRCW06030000Z0EA)
R131  ValueDisplayed: 51.1  [0402]  (hidden comment: CRCW040251R1FKED)
R132  ValueDisplayed: 0  [0603]  (hidden comment: CRCW06030000Z0EA)
R133  ValueDisplayed: DNP  [0603]  (hidden comment: RC0603JR-070RL)
R134  ValueDisplayed: 499  [0603]  (hidden comment: CRCW0603499RFKEA)
R135  ValueDisplayed: DNP  [0603]  (hidden comment: CRCW06031K00FKEA)
R136  ValueDisplayed: 499  [0603]  (hidden comment: CRCW0603499RFKEA)
R137  ValueDisplayed: 0  [0603]  (hidden comment: CRCW06030000Z0EA)
R138  ValueDisplayed: 51.1  [0402]  (hidden comment: CRCW040251R1FKED)
R139  ValueDisplayed: 0  [0603]  (hidden comment: CRCW06030000Z0EA)
R140  ValueDisplayed: DNP  [0603]  (hidden comment: RC0603JR-070RL)
T1  HMU1228NL  [FP-HMU1228NL_SMT_TRANSFORMER_8MM89_10MM09-MFG]
T2  HMU1228NL  [FP-HMU1228NL_SMT_TRANSFORMER_8MM89_10MM09-MFG]
U6  DESD1CAN2SOQ-7  VRWM: 24V  [FP-DESD1CAN2SOQ-7_SOT23-MFG]
U7  DESD1CAN2SOQ-7  VRWM: 24V  [FP-DESD1CAN2SOQ-7_SOT23-MFG]

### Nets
GND: C72.2 C73.1 C74.1 C75.1 C78.2 C79.1 C80.1 C81.1 J8.3 U6.3 U7.3
BQ0_CT_H: C74.2 T1.2(TCT)
BQ0_CT_L: C80.2 T2.2(TCT)
COMH_ISO_N: J7.4 L2.4 R129.2
COMH_ISO_P: J7.3 L2.3 R122.2
COMH_N: R126.1
COMH_P: R119.1
COMH_R1_N: C75.2 J8.2 R124.1 R125.1 R126.2 R127.1
COMH_R1_P: C72.1 J8.1 R119.2 R120.1 R123.2 R124.2
COMH_R2_N: R127.2 R128.1 U6.2
COMH_R2_P: R120.2 R121.1 U6.1
COMHC_N: C76.2 L2.1 R129.1 T1.4(TX-)
COMHC_P: C71.2 L2.2 R122.1 T1.6(TX+)
COMHR_N: C76.1 R128.2 T1.3(TD-)
COMHR_P: C71.1 R121.2 T1.1(TD+)
COML_ISO_N: J9.1 L3.3 R140.2
COML_ISO_P: J9.2 L3.4 R133.2
COML_N: R137.1
COML_P: R130.1
COML_R1_N: C81.2 J8.4 R135.1 R136.1 R137.2 R138.1
COML_R1_P: C78.1 J8.5 R130.2 R131.1 R134.2 R135.2
COML_R2_N: R138.2 R139.1 U7.1
COML_R2_P: R131.2 R132.1 U7.2
COMLC_N: C82.2 L3.2 R140.1 T2.6(TX+)
COMLC_P: C77.2 L3.1 R133.1 T2.4(TX-)
COMLR_N: C82.1 R139.2 T2.1(TD+)
COMLR_P: C77.1 R132.2 T2.3(TD-)
NetC73_2: C73.2 R123.1 R125.2
NetC79_2: C79.2 R134.1 R136.2

Not connected (* = marked no-connect by the designer): J7 1 2; J9 3 4; T1 5(CMT); T2 5(CMT)

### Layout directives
differential pair: COMH_ISO_N, COMH_ISO_P, COMH_N, COMH_P, COMH_R1_N, COMH_R1_P, COMH_R2_N, COMH_R2_P, COMHC_N, COMHC_P, COMHR_N, COMHR_P, COML_ISO_N, COML_ISO_P, COML_N, COML_P, COML_R1_N, COML_R1_P, COML_R2_N, COML_R2_P, COMLC_N, COMLC_P, COMLR_N, COMLR_P

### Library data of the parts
C71 C76 C77 C82 = CMP-0090879-1: 2200pF ±10% 2000V (2kV) Ceramic Capacitor X7R (2R1) 1206 (3216 Metric); Manufacturer: Knowles Syfer; TempCo: 15%; AEC Grade: Grade 1; AEC Qualified: Yes; SizeZ_mm: 1.7mm; Value: 2.2nF
C72 C75 C78 C81 = CMP-0006316-2: CAP, CERM, 220 pF, 50 V, +/- 10%, X7R, AEC-Q200 Grade 1, 0402; Manufacturer: TDK; TaMin_C: -55°C; ESR_ohm: 9.829; Polarized: N; SizeAreaWB_mm2: 3; Value1: 9.829 ohm; U/M: EA; Value: 220pF; TaMax_C: 125°C; SizeZ_mm: 0.6; SizeX_mm: 1; SizeY_mm: 0.5; AEC Qualified: Y; IRMS_A: 2.01345dA; AEC Category: Q200
C73 C79 = CMP-0007143-4: CAP, CERM, 0.01 uF, 50 V, +/- 10%, X7R, AEC-Q200 Grade 1, 0603; Manufacturer: MuRata; TaMin_C: -55°C; Polarized: N; SizeAreaWB_mm2: 4.68; Value1: Unknown; U/M: EA; Value: 0.01uF; TaMax_C: 125°C; SizeZ_mm: 1; SizeX_mm: 1.6; SizeY_mm: 0.8; SizeArea_mm2: 1.28; AEC Qualified: Y; AEC Category: Q200
C74 C80 = CMP-0750041-1: CAP, CERM, 100 pF, 50 V,+/- 5%, C0G/NP0, AEC-Q200 Grade 1, 0603; Manufacturer: MuRata; TaMin_C: -55°C; Polarized: N; SizeAreaWB_mm2: 4.68; U/M: EA; Value: 100pF; TaMax_C: 125°C; SizeZ_mm: 1; SizeX_mm: 1.6; SizeY_mm: 0.8; Value2: 50V; SizeArea_mm2: 1.28; AEC Qualified: Y; AEC Category: Q200
J7 J9 = CMP-0055239-1: Header(shrouded), 2.54mm, 4x1, R/A, Gold, TH; Manufacturer: Molex; CNHeader: FALSE; Current_A: 3A; Green_Lifecycle: Active; Shrouded: Y; Gender: Male; Green_REACh: Passed; Voltage_V: 250V; Row_Count: 1; Pitch_mm: 2.54
J8 = CMP-0075411-1: Header, 100mil, 5x1, Gold, TH; Manufacturer: Samtec; Pitch_mm: 2.54; Cert_VDE: N; Gender: Male; Cert_CSA: Y; Voltage_V: 550V; Green_REACh: Passed; Current_A: 6.3A; CT: False; Green_Lifecycle: Active; Row_Count: 1; CNHeader: True
L2 L3 = CMP-0093758-1: 100 µH @ 100 kHz 2 Line Common Mode Choke Surface Mount 150mA DCR 1.5Ohm; Manufacturer: TDK; DCR_ohm: 1.5; Tolerance_%: +50/-30%; AEC Grade: Grade 1; Test Frequency: 100kHz; SizeZ_mm: 2.5mm; AEC Qualified: Yes
R119 R121 R126 R128 R130 R132 R137 R139 = CMP-0025697-4: RES, 0, 5%, 0.1 W, AEC-Q200 Grade 0, 0603; Manufacturer: Vishay-Dale; Power_W: 100mW; TempCo: 200 ppm/C; Value_Code: 0000; Value: 0; EIA_Code: E24; SizeX_mm: 1.6; SizeY_mm: 0.8; SizeZ_mm: 1; Value2: 0.1W; SizeArea_mm2: 1.28; AEC Qualified: Y; VDC_V: 75V; AEC Category: Q200
R120 R127 R131 R138 = CMP-0026438-2: RES, 51.1, 1%, 0.063 W, AEC-Q200 Grade 0, 0402; Manufacturer: Vishay-Dale; Power_W: 63mW; TempCo: 100 ppm/C; Value_Code: 51R1; Value: 51.1; EIA_Code: E96; SizeX_mm: 1; SizeY_mm: 0.5; SizeZ_mm: 0.6; Value2: 0.063W; AEC Qualified: Y; VDC_V: 50V; AEC Category: Q200; AEC Grade: 0
R122 R129 R133 R140 = CMP-0025885-5: RES, 0, 5%, 0.1 W, 0603; Manufacturer: Yageo; Power_W: 100mW; TempCo: 200 ppm/C; Value_Code: 0000; Value: 0; EIA_Code: E24; SizeX_mm: 1.6; SizeZ_mm: 1; Value2: 0.1W; SizeArea_mm2: 1.28; AEC Qualified: N; VDC_V: 75V; AEC Category: Q200; SizeY_mm: 0.8; SizeAreaWB_mm2: 4.68
R123 R125 R134 R136 = CMP-0022446-5: RES, 499, 1%, 0.1 W, AEC-Q200 Grade 0, 0603; Manufacturer: Vishay-Dale; Power_W: 100mW; TempCo: 100 ppm/C; Value_Code: 499R; Value: 499; EIA_Code: E96; SizeX_mm: 1.6; SizeY_mm: 0.8; SizeZ_mm: 1; Value2: 0.1W; SizeArea_mm2: 1.28; AEC Qualified: Y; VDC_V: 75V; AEC Category: Q200; AEC Grade: 0
R124 R135 = CMP-0022109-5: RES, 1.00 k, 1%, 0.1 W, AEC-Q200 Grade 0, 0603; Manufacturer: Vishay-Dale; Power_W: 100mW; TempCo: 100 ppm/C; Value_Code: 1k00; Value: 1.00k; EIA_Code: E96; Res_ohm: 1k; SizeX_mm: 1.6; SizeY_mm: 0.8; SizeZ_mm: 1; Value2: 0.1W; SizeArea_mm2: 1.28; AEC Qualified: Y; VDC_V: 75V; AEC Category: Q200; AEC Grade: 0
T1 T2 = CMP-0086619-1: BMS TRANSFORMER; Manufacturer: Pulse; Ns1toNp: 1:1; Ind_H: 150µH; SizeZ_mm: 6.85mm; AEC Grade: Grade 1; AEC Qualified: Yes
U6 U7 = CMP-0125207-1: ESD Suppressor Diode TVS Bi-Dir 24V 70Vc Automotive AEC-Q101 3-Pin SOT-23 T/R; Manufacturer: Diodes Inc.; AEC Qualified: Yes; SizeZ_mm: 1.1mm; Ipp: 3A; Ppk: 200W; AEC Grade: Grade 0; Breakdown Voltage: 25.4V; Cap_F: 11pF; Clamping Voltage: 70V; Direction: Bidirectional; Number Of Channels: 2; Standoff Height: 0.013mm; TJmax_C: +150°C

## Sheet MCU136A_Hardware.SchDoc
size A3; Date: Not shown in title block; ApprovedBy: Not shown in title block; CheckedBy: Not shown in title block; Author: Not shown in title block; CompanyName: Not shown in title block; Engineer: Not shown in title block; Organization: Not shown in title block; Address1: Not shown in title block; Address2: Not shown in title block; Address3: Not shown in title block; Address4: Not shown in title block; DocumentNumber: 6; Revision: Use project parameter SCH_Rev; SheetNumber: 6; SheetTotal: 6; PageSetup: Record=PageOptions¦CenterHorizontal=True¦CenterVertical=True¦PrintScale=1.00¦XCorrection=1.00¦YCorrection=1.00¦PrintKind=0¦BorderSize=5000000¦LeftOffset=0¦BottomOffset=0¦Orientation=2¦PaperLength=1000¦PaperWidth=1000¦Scale=100¦PaperSource=15¦PrintQuality=600¦MediaType=1¦DitherType=10¦PaperKind=Letter¦PrintScaleMode=1
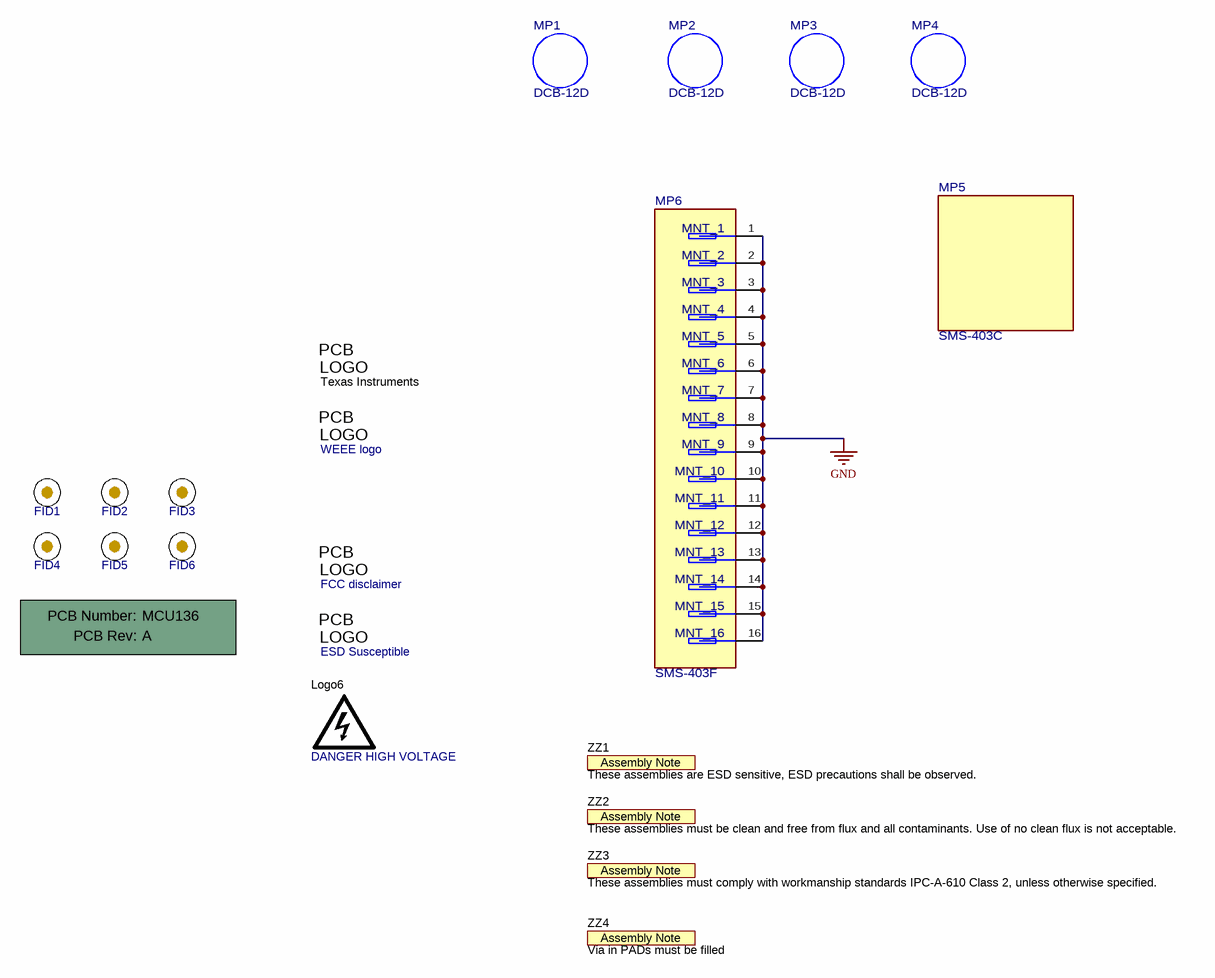
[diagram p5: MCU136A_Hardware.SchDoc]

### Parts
!PCB1  Printed Circuit Board  (value not drawn)  (mechanical)
FID1  Fiducial  [Fiducial10-30]  (value not drawn)  (no BOM)
FID2  Fiducial  [Fiducial10-30]  (value not drawn)  (no BOM)
FID3  Fiducial  [Fiducial10-30]  (value not drawn)  (no BOM)
FID4  Fiducial  [Fiducial10-30]  (value not drawn)  (no BOM)
FID5  Fiducial  [Fiducial10-30]  (value not drawn)  (no BOM)
FID6  Fiducial  [Fiducial10-30]  (value not drawn)  (no BOM)
Logo1  Texas Instruments  [TI_Horizontal_Overlay_Small]  (no BOM)
Logo2  WEEE logo  [WEEE_Minimum]  (no BOM)
Logo4  FCC disclaimer  [FCC_disclaimer]  (no BOM)
Logo5  ESD Susceptible  [ESD_Overlay_Medium]  (no BOM)
Logo6  DANGER HIGH VOLTAGE  [IEC_HighVoltage_Small]  (no BOM)
MP1  DCB-12D  [FP-DCB-12D_SPACER-MFG]
MP2  DCB-12D  [FP-DCB-12D_SPACER-MFG]
MP3  DCB-12D  [FP-DCB-12D_SPACER-MFG]
MP4  DCB-12D  [FP-DCB-12D_SPACER-MFG]
MP5  SMS-403C  [FP-SMS-403C_RF_SHLD-MFG]
MP6  SMS-403F  [FP-SMS-403F_SMT_SHIELD-MFG]
ZZ1  These assemblies are ESD sensitive, ESD precautions shall be observed.  [AssemblyNote]  (no BOM)
ZZ2  These assemblies must be clean and free from flux and all contaminants. Use of no clean flux is not acceptable.  [AssemblyNote]  (no BOM)
ZZ3  These assemblies must comply with workmanship standards IPC-A-610 Class 2, unless otherwise specified.  [AssemblyNote]  (no BOM)
ZZ4  Via in PADs must be filled  [AssemblyNote]  (no BOM)

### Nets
GND: MP6.1(MNT_1) MP6.2(MNT_2) MP6.3(MNT_3) MP6.4(MNT_4) MP6.5(MNT_5) MP6.6(MNT_6) MP6.7(MNT_7) MP6.8(MNT_8) MP6.9(MNT_9) MP6.10(MNT_10) MP6.11(MNT_11) MP6.12(MNT_12) MP6.13(MNT_13) MP6.14(MNT_14) MP6.15(MNT_15) MP6.16(MNT_16)

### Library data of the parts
!PCB1 = CMP-0003618-2: Manufacturer: Any; PartNumber: MCU136
FID1-FID6 = CMP-0077181-1: Fiducial mark.  There is nothing to buy or mount.
Logo1 = CMP-0074838-1: Texas Instrument Corporate Signature; SymbolCreator: a0412235; Lib Reference: TI_Logo
Logo2 = CMP-0074769-1
Logo4 = CMP-0074847-1: FCC_disclaimer
Logo5 = CMP-0074840-1: ESD Susceptible Symbol; SymbolCreator: a0412235; Lib Reference: ESD_Susceptible
Logo6 = CMP-0074835-1: IEC 61010-1 High Voltage Warning; SymbolCreator: a0412235
MP1-MP4 = CMP-0016301-1: Spacer Support Nylon 66 Natural; Manufacturer: Kang Yang USA; AEC Qualified: No
MP5 = CMP-0120478-1: RF Shield Cover 1.058" (26.87mm) X 1.058" (26.87mm) Non-Vented Surface Mount; Manufacturer: Leader Tech; AEC Qualified: No; SizeZ_mm: 0.084inch
MP6 = CMP-0086879-1: RF SHIELD 1.034" X 1.034" SMD; Manufacturer: Leader Tech
ZZ1 = CMP-0077236-1
ZZ2 = CMP-0077237-1
ZZ3 = CMP-0077238-1
ZZ4 = CMP-0077238-1: These assemblies must comply with workmanship standards IPC-A-610 Class 2, unless otherwise specified.

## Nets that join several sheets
CELL18_Lad: MCU136A_Connector (J2.1), MCU136A_Resistive_Ladder (R159.2 S4.6)
GND: MCU136A_RF (64 pins), MCU136A_BQ7971x (41 pins), MCU136A_Connector (5 pins), MCU136A_Communication (11 pins), MCU136A_Hardware (16 pins)
WL_PWR: MCU136A_RF (6 pins), MCU136A_BQ7971x (S3.4)
BAT: MCU136A_BQ7971x (C11.1 R13.2 TP2.1 U2.1), MCU136A_Connector (C18.1)
BB: MCU136A_BQ7971x (U2.20), MCU136A_Connector (15 pins)
CB0: MCU136A_BQ7971x (U2.39), MCU136A_Connector (C67.2 C69.1 R106.2 R108.2)
CB1: MCU136A_BQ7971x (U2.37), MCU136A_Connector (C65.2 C67.1 R101.2 R104.2)
CB2: MCU136A_BQ7971x (U2.35), MCU136A_Connector (C63.2 C65.1 R97.2 R99.2)
CB3: MCU136A_BQ7971x (U2.33), MCU136A_Connector (C61.2 C63.1 R94.2 R96.2)
CB4: MCU136A_BQ7971x (U2.31), MCU136A_Connector (C57.2 C61.1 R91.2 R93.2)
CB5: MCU136A_BQ7971x (U2.29), MCU136A_Connector (C52.2 C57.1 R86.2 R89.2)
CB6: MCU136A_BQ7971x (U2.27), MCU136A_Connector (C47.2 C52.1 R81.2 R83.2)
CB7: MCU136A_BQ7971x (U2.25), MCU136A_Connector (5 pins)
CB8: MCU136A_BQ7971x (U2.23), MCU136A_Connector (5 pins)
CB9: MCU136A_BQ7971x (U2.21), MCU136A_Connector (5 pins)
CB10: MCU136A_BQ7971x (U2.18), MCU136A_Connector (5 pins)
CB11: MCU136A_BQ7971x (U2.16), MCU136A_Connector (5 pins)
CB12: MCU136A_BQ7971x (U2.14), MCU136A_Connector (5 pins)
CB13: MCU136A_BQ7971x (U2.12), MCU136A_Connector (5 pins)
CB14: MCU136A_BQ7971x (U2.10), MCU136A_Connector (C25.2 C27.1 R40.2 R42.2)
CB15: MCU136A_BQ7971x (U2.8), MCU136A_Connector (C23.2 C25.1 R37.2 R39.2)
CB16: MCU136A_BQ7971x (U2.6), MCU136A_Connector (C21.2 C23.1 R34.2 R36.2)
CB17: MCU136A_BQ7971x (U2.4), MCU136A_Connector (C19.2 C21.1 R31.2 R33.2)
CB18: MCU136A_BQ7971x (U2.2), MCU136A_Connector (C18.2 C19.1 R28.2 R30.2)
CELL0: MCU136A_Connector (5 pins), MCU136A_Resistive_Ladder (R176.1)
CELL1: MCU136A_Connector (5 pins), MCU136A_Resistive_Ladder (S6.12)
CELL2: MCU136A_Connector (5 pins), MCU136A_Resistive_Ladder (S6.11)
CELL3: MCU136A_Connector (5 pins), MCU136A_Resistive_Ladder (S6.10)
CELL4: MCU136A_Connector (5 pins), MCU136A_Resistive_Ladder (S6.9)
CELL5: MCU136A_Connector (5 pins), MCU136A_Resistive_Ladder (S6.8)
CELL6: MCU136A_Connector (5 pins), MCU136A_Resistive_Ladder (S6.7)
CELL7: MCU136A_Connector (5 pins), MCU136A_Resistive_Ladder (S5.12)
CELL8: MCU136A_Connector (5 pins), MCU136A_Resistive_Ladder (S5.11)
CELL9: MCU136A_Connector (5 pins), MCU136A_Resistive_Ladder (S5.10)
CELL10: MCU136A_Connector (5 pins), MCU136A_Resistive_Ladder (S5.9)
CELL11: MCU136A_Connector (5 pins), MCU136A_Resistive_Ladder (S5.8)
CELL12: MCU136A_Connector (5 pins), MCU136A_Resistive_Ladder (S5.7)
CELL13: MCU136A_Connector (5 pins), MCU136A_Resistive_Ladder (S4.12)
CELL14: MCU136A_Connector (5 pins), MCU136A_Resistive_Ladder (S4.11)
CELL15: MCU136A_Connector (5 pins), MCU136A_Resistive_Ladder (S4.10)
CELL16: MCU136A_Connector (5 pins), MCU136A_Resistive_Ladder (S4.9)
CELL17: MCU136A_Connector (5 pins), MCU136A_Resistive_Ladder (S4.8)
CELL18: MCU136A_Connector (5 pins), MCU136A_Resistive_Ladder (S4.7)
COMH_N: MCU136A_BQ7971x (U2.45), MCU136A_Communication (R126.1)
COMH_P: MCU136A_BQ7971x (U2.46), MCU136A_Communication (R119.1)
COML_N: MCU136A_BQ7971x (U2.44), MCU136A_Communication (R137.1)
COML_P: MCU136A_BQ7971x (U2.43), MCU136A_Communication (R130.1)
FAULT_WL: MCU136A_RF (U13.11), MCU136A_BQ7971x (S1.3)
UART_RX_WL: MCU136A_RF (U13.13), MCU136A_BQ7971x (R5.1)
UART_TX_WL: MCU136A_RF (U13.10), MCU136A_BQ7971x (R6.1)
VC0: MCU136A_BQ7971x (U2.40), MCU136A_Connector (C68.2 C70.1 R107.2)
VC1: MCU136A_BQ7971x (U2.38), MCU136A_Connector (C66.2 C68.1 R103.2)
VC2: MCU136A_BQ7971x (U2.36), MCU136A_Connector (C64.2 C66.1 R98.2)
VC3: MCU136A_BQ7971x (U2.34), MCU136A_Connector (C62.2 C64.1 R95.2)
VC4: MCU136A_BQ7971x (U2.32), MCU136A_Connector (C58.2 C62.1 R92.2)
VC5: MCU136A_BQ7971x (U2.30), MCU136A_Connector (C54.2 C58.1 R88.2)
VC6: MCU136A_BQ7971x (U2.28), MCU136A_Connector (C49.2 C54.1 R82.2)
VC7: MCU136A_BQ7971x (U2.26), MCU136A_Connector (C44.2 C49.1 C59.1 R77.2)
VC8: MCU136A_BQ7971x (U2.24), MCU136A_Connector (C39.2 C44.1 C56.1 R70.2)
VC9: MCU136A_BQ7971x (U2.22), MCU136A_Connector (C36.2 C39.1 C53.1 R67.2)
VC10: MCU136A_BQ7971x (U2.19), MCU136A_Connector (C34.2 C36.1 C50.1 R63.2)
VC11: MCU136A_BQ7971x (U2.17), MCU136A_Connector (C32.2 C34.1 C46.1 R58.2)
VC12: MCU136A_BQ7971x (U2.15), MCU136A_Connector (C30.2 C32.1 C43.1 R51.2)
VC13: MCU136A_BQ7971x (U2.13), MCU136A_Connector (C28.2 C30.1 C40.1 R46.2)
VC14: MCU136A_BQ7971x (U2.11), MCU136A_Connector (C26.2 C28.1 R41.2)
VC15: MCU136A_BQ7971x (U2.9), MCU136A_Connector (C24.2 C26.1 R38.2)
VC16: MCU136A_BQ7971x (U2.7), MCU136A_Connector (C22.2 C24.1 R35.2)
VC17: MCU136A_BQ7971x (U2.5), MCU136A_Connector (C20.2 C22.1 R32.2)
VC18: MCU136A_BQ7971x (U2.3), MCU136A_Connector (C20.1 R29.2)
VPWR: MCU136A_BQ7971x (R4.2 R13.1), MCU136A_Connector (D4.1 J2.2 J3.14 TP8.1)

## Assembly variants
001: not fitted C7 C38 C40 C41 C43 C45 C46 C51 C53 C55 C56 C59 C60 C92 C100 R44 R48 R53 R56 R60 R72 R75 R79 R84 R112 R113 R114 R116 R117 R118 R122 R124 R129 R133 R135 R140 R153 R155 R156 R157 T1 T2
